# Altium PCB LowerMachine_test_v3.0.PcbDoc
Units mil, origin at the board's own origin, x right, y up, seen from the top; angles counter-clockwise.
Board outline 1968.5 x 1968.5 mil, 2 copper layers (Top Layer, Bottom Layer); 43 components, 58 nets, 180 pads, 51 vias.
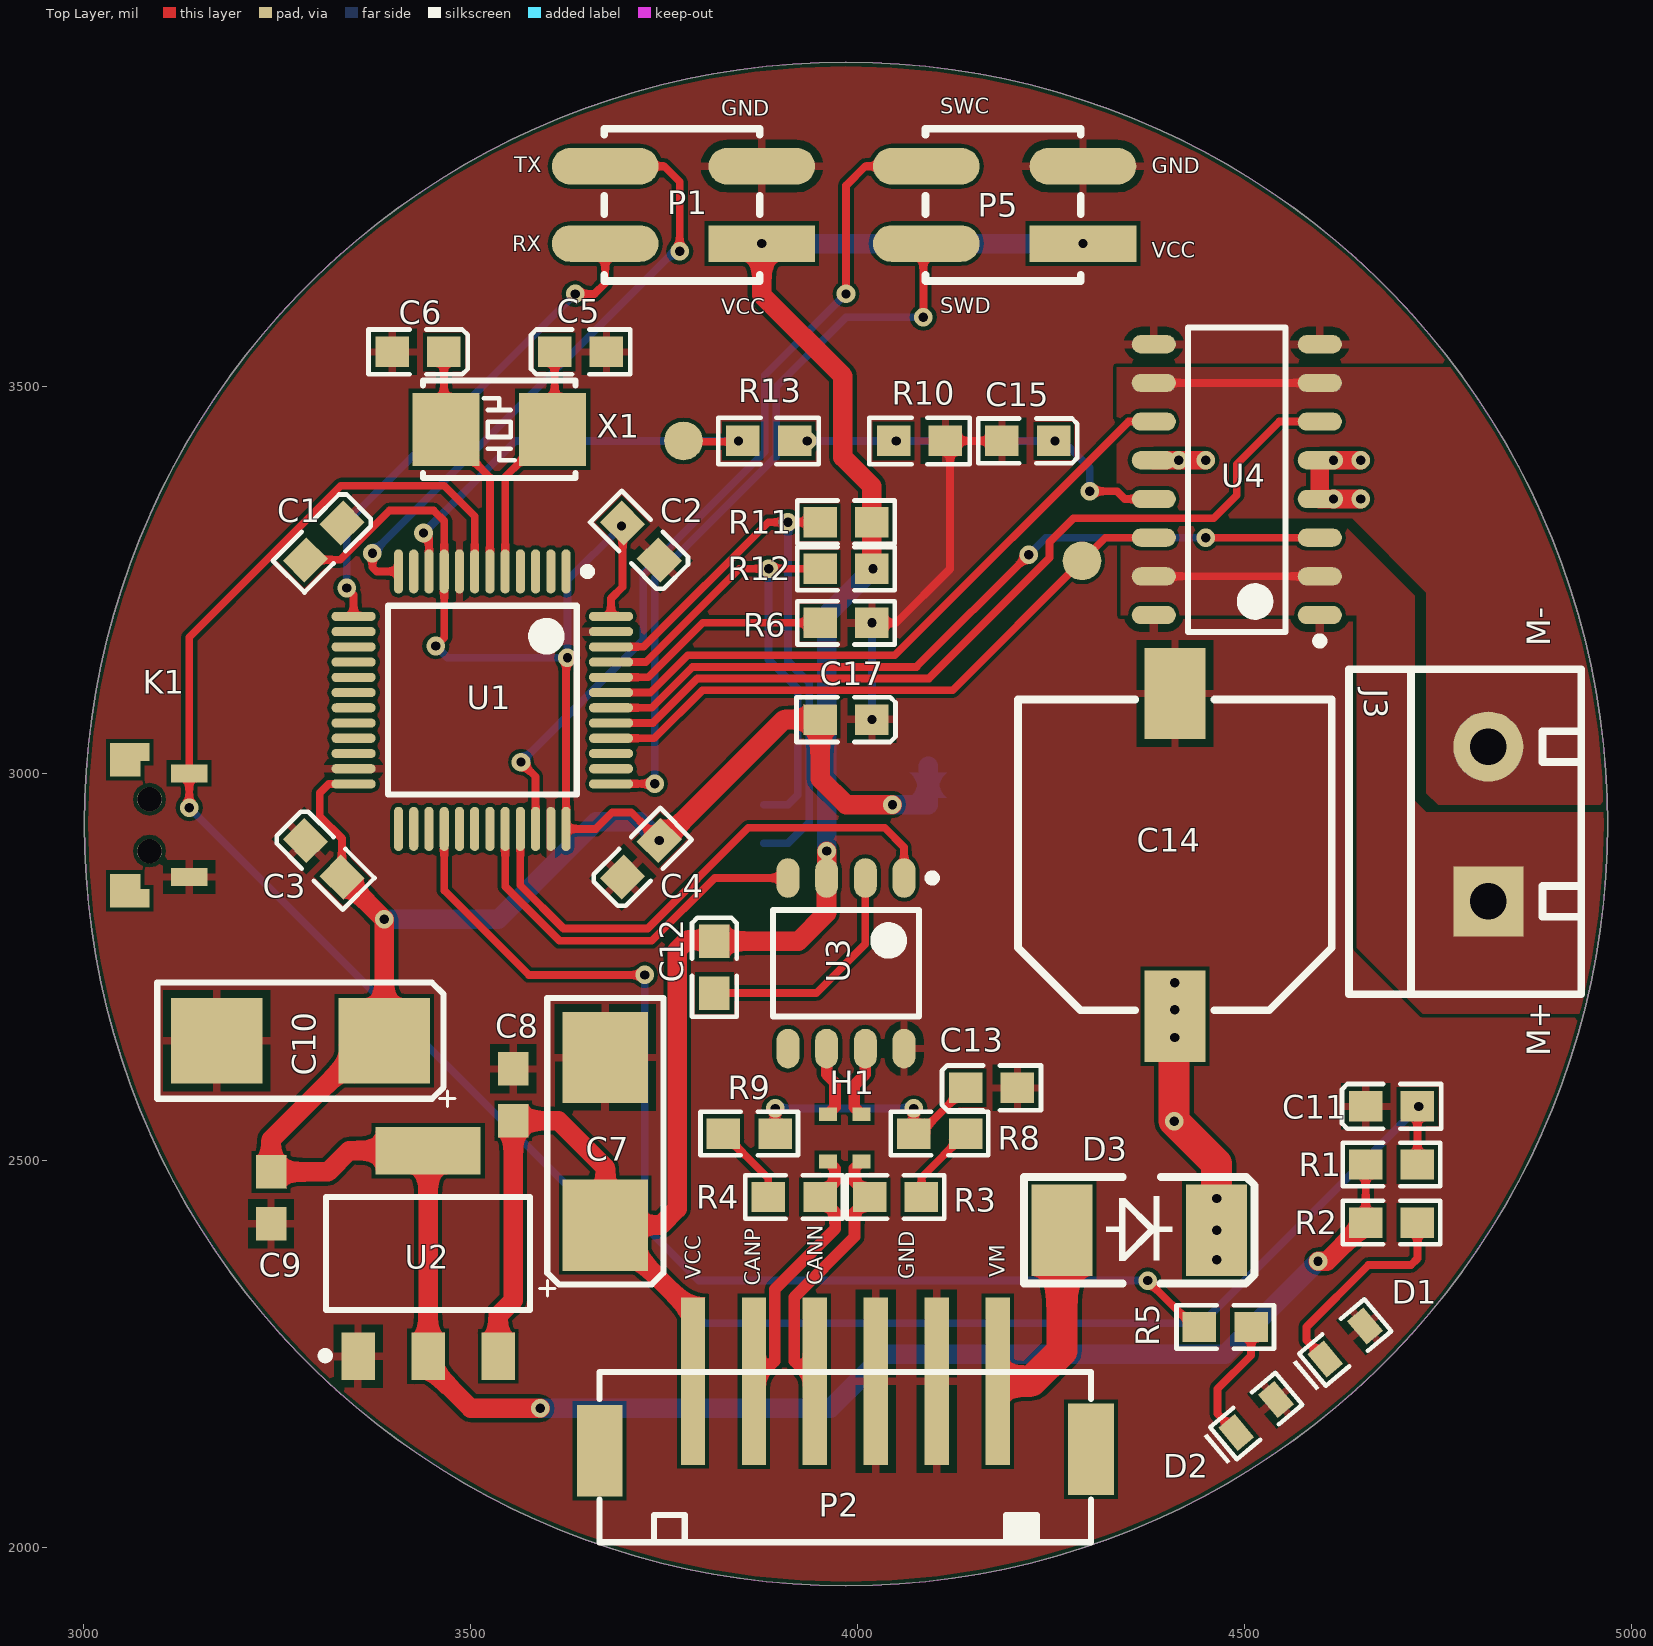
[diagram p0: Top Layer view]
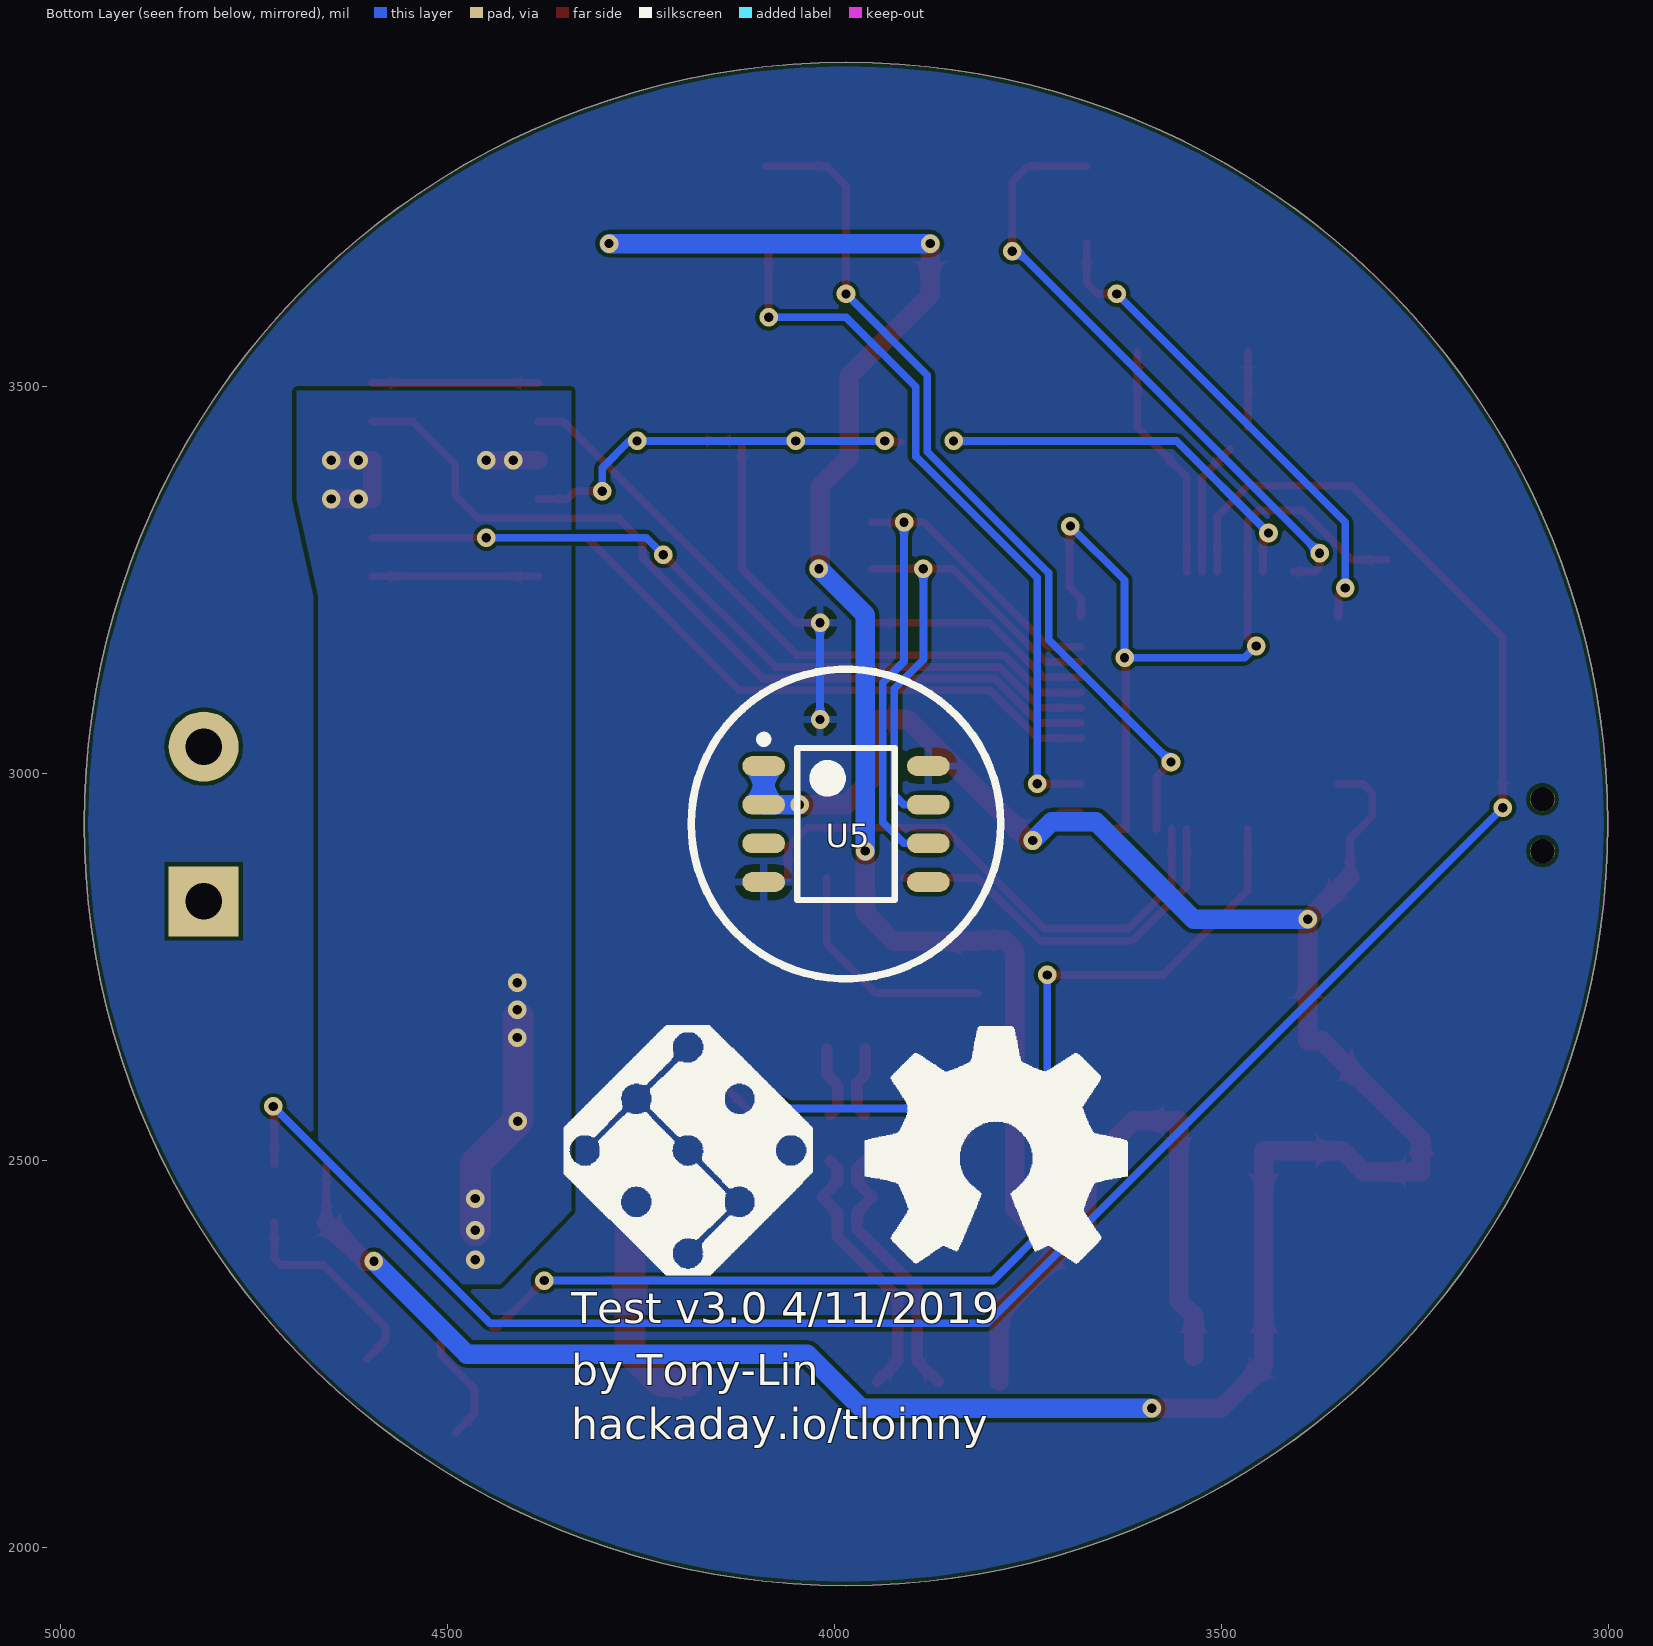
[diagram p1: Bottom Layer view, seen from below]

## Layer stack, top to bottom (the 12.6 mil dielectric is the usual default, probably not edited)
Top Solder: solder mask 0.4, Solder Resist, Dk 3.5
Top Layer: signal copper 1.4
Dielectric 1: dielectric 12.6, FR-4, Dk 4.8
Bottom Layer: signal copper 1.4
Bottom Solder: solder mask 0.4, Solder Resist, Dk 3.5

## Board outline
3000.75,2935 ccw(c3985,2935) 3985,1950.75 ccw(c3985,2935) 4969.25,2935 ccw(c3985,2935) 3985,3919.25 ccw(c3985,2935)

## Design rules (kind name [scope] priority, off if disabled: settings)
Clearance [All] p1: gap=5
DiffPairsRouting [All] p1: maxlimit=10 minlimit=10 mostfreqgap=10 toplayer_minwidth=15 toplayer_maxwidth=15 toplayer_prefwidth=15 bottomlayer_minwidth=15 bottomlayer_maxwidth=15 bottomlayer_prefwidth=15 maxuncoupledlength=500
PolygonConnect PolygonConnect_3 [InNet('24V')] p1: connectstyle=Direct reliefconductorwidth=10 reliefentries=4 polygonreliefangle="90 Angle" airgapwidth=10
PolygonConnect PolygonConnect_2 [InNet('GND')] p2: connectstyle=Relief reliefconductorwidth=10 reliefentries=4 polygonreliefangle="90 Angle" airgapwidth=10
PolygonConnect PolygonConnect_1 [InNet('M+')] p3: connectstyle=Direct reliefconductorwidth=10 reliefentries=4 polygonreliefangle="90 Angle" airgapwidth=10
PolygonConnect [InNet('M-')] p4: connectstyle=Direct reliefconductorwidth=10 reliefentries=4 polygonreliefangle="90 Angle" airgapwidth=10
RoutingVias [All] p1: holewidth=28 width=50 viastyle="Through Hole" minholewidth=28 minwidth=50 maxholewidth=28 maxwidth=50
SolderMaskExpansion [All] p1: expansion=4
Width [All] p1: maxlimit=40 minlimit=6 preferedwidth=10
29 further rules are at their usual default settings.

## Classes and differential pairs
differential pair IN: +IN_P -IN_N
differential pair CAN: +CAN_P -CAN_N

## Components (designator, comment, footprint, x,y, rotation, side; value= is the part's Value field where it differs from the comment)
C1 "104" Cap-0603 3310,3300 r225 top
C2 "104" Cap-0603 3720,3300 r135 top
C3 "104" Cap-0603 3310,2890 r315 top
C4 "104" Cap-0603 3720,2890 r45 top
C5 "22pf" Cap-0603 3642,3545 r0 top
C6 "22pf" Cap-0603 3432,3545 r180 top
C7 "100uf" tan_cap_C 3674,2525 r90 top
C8 "104" Cap-0603-M 3555,2585 r270 top
C9 "104" Cap-0603-M 3242,2452 r90 top
C10 "100uf" tan_cap_C 3280,2655 r180 top
C11 "105" Cap-0603 4690,2570 r0 top
C12 "104" Cap-0603 3815,2750 r270 top
C13 "100nf" Cap-0603 4173,2594 r0 top
C14 "35v 470uf" CAPE_G_10X10.3X10.2 4410,2895 r270 top
C15 "10nf" Cap-0603 4220,3430 r180 top
C17 "100nf" Cap-0603 3985,3070 r180 top
D1 "LED_SMD_BLUE" LED_0603_B 4630,2265 r40 top
D2 "LED_SMD_WHITE" LED_0603_W 4515,2170 r40 top
D3 "1N5824" DO-214AC/SMA 4269,2410 r0 top
H1 "共模扼流圈" 共模扼流圈 4005,2560 r270 top
J3 "Motor interface" KF301-5.0-2P 4815,2835 r90 top
K1 "KEY" SW-SMD-2X4 3085,2900 r90 top
P1 "Header_2X2" Header_SMD_2.54X2 3775,3735 r90 top
P2 "PH2.0-6P" PH2.0S-6P 4181,2215 r180 top
P5 "Header_2X2" Header_SMD_2.54X2 4190,3735 r90 top
R1 "10K" Res-0603 4690,2495 r0 top
R2 "470R" Res-0603 4690,2420 r0 top
R3 "60R" Res-0603 4049,2453 r0 top
R4 "60R" Res-0603 3918,2453 r0 top
R5 "470" Res-0603 4475,2285 r0 top
R6 "10K" Res-0603 3985,3195 r180 top
R8 "0R" Res-0603 4106,2535 r180 top
R9 "0R" Res-0603 3860,2535 r180 top
R10 "1K" Res-0603 4080,3430 r180 top
R11 "4.7K" Res-0603 3985,3325 r180 top
R12 "4.7K" Res-0603 3985,3265 r180 top
R13 "10K" Res-0603 3885,3430 r0 top
U1 "stm32f103c8t6" stm32f103c8t6 3515,3095 r270 top
U2 "AMS1117" AMS1117 3445,2380 r0 top
U3 "tja1050" tja1050 3985,2755 r270 top
U4 "VNH7100" VNH7100 4490,3380 r180 top
U5 "AS5600" AS5600 3985,2935 r180 bottom
X1 "XTAL-2P" "OSC 5032-2P" 3537,3445 r0 top

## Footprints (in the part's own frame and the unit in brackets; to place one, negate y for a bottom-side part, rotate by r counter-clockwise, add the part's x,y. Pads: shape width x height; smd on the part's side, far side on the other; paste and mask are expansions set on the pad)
AMS1117 [mm]
  rect 1.1x1.55 smd: 1(-2.3,-3.375) 2(0,-3.375) 3(2.3,-3.375)
  rect 3.45x1.55 smd: 4(0,3.375)
  silkscreen extent -3.5,-3.48 3.35,1.85, body extent -3.25,-3.48 3.25,3.48, height 1.7
AS5600 [mm] "SOIC, 8-Leads, Body 4.90x3.90mm, Pitch 1.27mm, Thermal Pad 0.00x0.00mm, IPC Medium Density"
  oval 1.4x0.65 smd: 1(-2.7,1.905) 2(-2.7,0.635) 3(-2.7,-0.635) 4(-2.7,-1.905) 5(2.7,-1.905) 6(2.7,-0.635) 7(2.7,0.635) 8(2.7,1.905)
  silkscreen extent -2.83,-2.5 1.6,2.9, body extent -2,-2.5 2,2.5, height 1.75
Cap-0603 [mm]
  rect 1.1x1 smd: 1(-0.85,0) 2(0.85,0)
  silkscreen extent -1.63,-0.74 1.63,0.74, body extent -0.8,-0.4 0.8,0.4, height 0.6
Cap-0603-M [mm]
  rect 1.1x1 smd: 1(-0.85,0) 2(0.85,0)
  body extent -0.8,-0.4 0.8,0.4, height 0.6
CAPE_G_10X10.3X10.2 [mm]
  rect 3x2 smd: 1(5.3,0) 2(-5.3,0)
  silkscreen extent -5.1,-5.15 5.1,5.15, body extent -5.8,-5.15 5.8,5.15, height 10.2
DO-214AC/SMA [mm] "塑封二极管"
  rect 2x3 smd: A(-0.127,0) K(4.953,0)
  silkscreen extent -1.37,-1.75 6.2,1.75, body extent 0.11,-1.35 4.71,1.35, height 2.4
Header_SMD_2.54X2 [mm]
  rect 1.2x3.5 smd: 1(-1.27,-2.57)
  oval 1.2x3.5 smd: 2(1.27,-2.57) 3(1.27,2.57) 4(-1.27,2.57)
  silkscreen extent -2.5,-2.5 2.5,2.6, body extent -2.58,-3.75 2.5,3.75, height 9.7
KF301-5.0-2P [mm] "可拼接端子/6A"
  rect 2.3x2.3 hole 1.2: 1(0,0)
  round 2.3 hole 1.2: 2(5.08,0)
  silkscreen extent -3.05,-3.05 7.62,4.57, body extent -3,-3.09 7.5,4.51, height 10.05
LED_0603_B [mm]
  rect 0.7x1 smd: 1(-0.85,0) 2(0.85,0)
  silkscreen extent -1.75,-0.69 1.4,0.69, body extent -0.8,-0.42 0.8,0.38, height 0.61
LED_0603_W [mm]
  rect 0.7x1 smd: 1(-0.85,0) 2(0.85,0)
  silkscreen extent -1.75,-0.69 1.4,0.69, body extent -0.8,-0.42 0.8,0.38, height 0.61
"OSC 5032-2P" [mm]
  rect 2.2x2.4 smd: 1(-1.75,0) 2(1.75,0)
  silkscreen extent -2.5,-1.6 2.5,1.6, body extent -2.5,-1.52 2.5,1.68, height 0.86
PH2.0S-6P [mm]
  rect 1.5x3 smd: 0(-3.064,2.238) 0(13.064,2.286)
  rect 0.8x5.5 smd: 1(0,0) 2(2,0) 3(4,0) 4(6,0) 5(8,0) 6(10,0)
  silkscreen extent -3.06,-0.3 13.06,5.29, body extent -3,-2.5 13,5.3, height 6.15
Res-0603 [mm]
  rect 1.1x1 smd: 1(-0.85,0) 2(0.85,0)
  silkscreen extent -1.6,-0.71 1.6,0.71, body extent -0.8,-0.4 0.8,0.4, height 0.38
stm32f103c8t6 [mm] "QFP, 100-Leads, Body 14.00x20.00mm, Pitch 0.65mm, IPC Medium Density"
  oval 1.45x0.3 smd: 1(-4.225,2.75) 2(-4.225,2.25) 3(-4.225,1.75) 4(-4.225,1.25) 5(-4.225,0.75) 6(-4.225,0.25) 7(-4.225,-0.25) 8(-4.225,-0.75) 9(-4.225,-1.25) 10(-4.225,-1.75) 11(-4.225,-2.25) 12(-4.225,-2.75) 25(4.225,-2.75) 26(4.225,-2.25) 27(4.225,-1.75) 28(4.225,-1.25) 29(4.225,-0.75) 30(4.225,-0.25) 31(4.225,0.25) 32(4.225,0.75) 33(4.225,1.25) 34(4.225,1.75) 35(4.225,2.25) 36(4.225,2.75)
  oval 0.3x1.45 smd: 13(-2.75,-4.225) 14(-2.25,-4.225) 15(-1.75,-4.225) 16(-1.25,-4.225) 17(-0.75,-4.225) 18(-0.25,-4.225) 19(0.25,-4.225) 20(0.75,-4.225) 21(1.25,-4.225) 22(1.75,-4.225) 23(2.25,-4.225) 24(2.75,-4.225) 37(2.75,4.225) 38(2.25,4.225) 39(1.75,4.225) 40(1.25,4.225) 41(0.75,4.225) 42(0.25,4.225) 43(-0.25,4.225) 44(-0.75,4.225) 45(-1.25,4.225) 46(-1.75,4.225) 47(-2.25,4.225) 48(-2.75,4.225)
  silkscreen extent -4.35,-3.1 3.1,3.58, body extent -3.5,-3.5 3.5,3.5, height 1.6
SW-SMD-2X4 [mm]
  rect 0.6x1.3 smd: 0(-1.55,0.65) 0(3.25,0.65)
  rect 0.6x1 smd: 0(-1.05,0.8) 0(2.75,0.8)
  round 0.8 hole 0.8: 0(0,0) 0(1.7,0)
  rect 0.6x1.2 smd: 1(-0.85,-1.3) 3(2.55,-1.3)
  body extent -2.97,-1.8 4.83,1.8, height 3.5
tan_cap_C [mm]
  rect 3x2.8 smd: 1(-2.75,0) 2(2.75,0)
  silkscreen extent -5.08,-1.91 4.7,2.16, body extent -3.15,-1.6 3.15,1.6, height 2.5
tja1050 [mm] "SOP, 8-Leads, Body 4.90x3.90mm, Pitch 1.27mm, IPC Medium Density"
  oval 1.3x0.75 smd: 1(-2.8,1.905) 2(-2.8,0.635) 3(-2.8,-0.635) 4(-2.8,-1.905) 5(2.8,-1.905) 6(2.8,-0.635) 7(2.8,0.635) 8(2.8,1.905)
  silkscreen extent -2.92,-2.4 1.75,2.96, body extent -1.9,-2.4 1.9,2.4, height 1.75
VNH7100 [mm] "SOIC, 16-Leads, Body 9.90x3.90mm, Pitch 1.27mm, IPC Medium Density"
  oval 1.45x0.6 smd: 1(-2.725,4.445) 2(-2.725,3.175) 3(-2.725,1.905) 4(-2.725,0.635) 5(-2.725,-0.635) 6(-2.725,-1.905) 7(-2.725,-3.175) 8(-2.725,-4.445) 9(2.725,-4.445) 10(2.725,-3.175) 11(2.725,-1.905) 12(2.725,-0.635) 13(2.725,0.635) 14(2.725,1.905) 15(2.725,3.175) 16(2.725,4.445)
  silkscreen extent -2.85,-5 1.6,5.42, body extent -2,-5 2,5, height 1.75
共模扼流圈 [mm]
  rect 0.45x0.6 smd: 1(0,0) 2(0,-1.1) 3(1.55,-1.1) 4(1.55,0)

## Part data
C1 C2 C3 C4 C5 C6 C8 C9 C11 C12 C13: library part CAP
C7 C10: library part tan_cap
C14: library part CAPE-SMD, "贴片电解电容"
C15 C17: library part CAP, "贴片陶瓷电容"
D1 D2: "发光二极管"
D3: library part DIODE, "普通二极管"
J3: library part KF301-2P
R1 R2 R3 R4 R5 R6 R8 R9 R10 R11 R12 R13: library part RES, "贴片电阻"
X1: "2脚无源脚晶振"

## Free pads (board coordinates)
  round 50 smd: 1(4290,3275) 2(3775,3430)

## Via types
v1: diameter 24, hole 12, Top Layer to Bottom Layer, 51 vias

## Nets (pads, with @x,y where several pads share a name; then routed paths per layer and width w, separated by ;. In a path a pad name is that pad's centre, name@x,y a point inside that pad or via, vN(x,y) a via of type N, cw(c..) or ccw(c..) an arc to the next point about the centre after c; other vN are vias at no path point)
3.3V: C1.2 C2.2 C3.2 C4.2 C9.2 C10.1 C17.2 R1.1 R2.1 U1.9 U1.24 U1.36 U1.48 U2.2 U2.4 U5.1 U5.2 | length 4760.9
  Top Layer w10: C1.2 3331.34,3276.34 3395,3340 3452.37,3340 3465.79,3326.59 U1.9 3465.79,3175.79 v1(3455,3165) ; C3.2 3333.66,2916.34 3305,2945 3305,2975 3316.73,2986.73 U1.24 ; v1(3625,3150) 3623.27,3148.27 U1.36 3661.66,2928.66 3683,2950 3707.33,2950 v1(3743.66,2913.66) ; U1.48 3681.34,3226.34 3696.34,3241.34 C2.2 ; R2.1 R1.1
  Top Layer w25: C3.2 v1(3388.27,2811.73) C10.1 3370,2655 3242,2527 C9.2 3315.46,2485.46 3342.87,2512.87 U2.4 U2.2 3445,2235 3500,2180 v1(3590,2180) ; v1(3743.66,2913.66) 3748.66,2913.66 3905,3070 C17.2 3951.54,2993.46 3985,2960 v1(4045,2960) ; v1(4595,2370) 4606.54,2370 R2.1
  Bottom Layer w10: v1(3455,3165) 3470,3150 v1(3625,3150) 3625,3250 v1(3695,3320)
  Bottom Layer w25: v1(3388.27,2811.73) 3535.73,2811.73 3662,2938 3719.33,2938 v1(3743.66,2913.66) ; v1(3590,2180) 3965,2180 4035,2250 4475,2250 v1(4595,2370) ; v1(4045,2960) U5.2 U5.1
24V: C14.1 D3.K U4.4 U4.5 U4.12 | length 520.8
  Top Layer w24: U4.12 v1(4450,3405) ; v1(4650,3355) U4.4 U4.5 v1(4650,3405)
  Top Layer w40: C14.1@4409,2685.34 4409,2592.34 v1(4409,2551) 4464,2496 v1(4464,2410)
  other v1: 4464,2372 4464,2451 4410,2659 4410,2695 4410,2730 4615,3355 4415,3405 4615,3405
ADC: pad.2 R13.1 U1.10 | length 585.4
  Top Layer w10: v1(3439,3311) 3446.1,3303.9 U1.10 ; pad.2 3776,3429 R13.1@3846.54,3429 ; v1(3846,3430) R13.1@3850.54,3430
  Bottom Layer w10: v1(3439,3311) 3558,3430 3775,3430 v1(3846,3430)
BOOT0: R6.2 U1.44 | length 299.4
  Top Layer w10: U1.44 3729.27,3124.53 3799.75,3195 R6.2
BOOT1: U1.20
CAN_N: H1.4 P2.4 R3.1 | length 347.7
  Top Layer w15: P2.4 3937.28,2222.5 3936.5,2222.5 3918,2241 3918,2323.64 3996,2401.64 3996,2433.46 R3.1 3996,2472.54 3996,2489.98 H1.4
CAN_P: H1.3 P2.5 R4.2 | length 348.1
  Top Layer w15: P2.5 3873.54,2222.5 3874.5,2222.5 3893,2241 3893,2334 3971,2412 3971,2433.46 R4.2 3971,2472.54 3971,2489.67 H1.3
CAN_RX: U1.32 U3.4 | length 502.6
  Top Layer w10: U1.32 3544.53,2854.26 3614.79,2784 3734,2784 3815.24,2865.24 U3.4
CAN_TX: U1.33 U3.1 | length 695.7
  Top Layer w10: U1.33 3564.21,2855.79 3620,2800 3728.79,2800 3858.79,2930 4035,2930 4060,2905 U3.1
GND: C1.1 C2.1 C3.1 C4.1 C5.2 C6.2 C7.2 C8.1 C9.1 C10.2 C11.1 C13.2 C14.2 C15.2 C17.1 D1.2 D2.2 K1.1 P1.2 P2.2 P2.3 P5.2 R6.1 R10.1 U1.8 U1.23 U1.35 U1.47 U2.1 U3.8 U4.1 U4.8 U4.9 U4.16 U5.4 U5.8 | length 492.4
  Top Layer w10: v1(4018.46,3195) 4050,3195 4119.46,3264.46 R10.1@4119.46,3429 ; R10.1 C15.2
  Bottom Layer w10: v1(4018.46,3070) v1(4018.46,3195)
IN_N: H1.1 U3.7 | length 94.4
  Top Layer w15: H1.1 3995.85,2569.15 3995.85,2597.52 4010,2611.67 U3.7
IN_P: H1.2 U3.6 | length 93
  Top Layer w15: U3.6 3960,2611.67 3970.85,2600.83 3970.85,2569.15 H1.2
JTCK: P5.4 U1.37 | length 958.7
  Top Layer w10: U1.37 3681.61,2987 v1(3738,2987) ; v1(4085,3590) 4085,3681.18 P5.4
  Bottom Layer w10: v1(3738,2987) 3738,3253 3895,3410 3895,3500 3985,3590 v1(4085,3590)
JTMS: P5.3 U1.34 | length 1127.3
  Top Layer w10: v1(3565,3015) 3583.9,2996.1 U1.34 ; v1(3985,3620) 3985,3760 4010,3785 P5.3
  Bottom Layer w10: v1(3565,3015) 3723,3173 3723,3259.21 3880,3416.21 3880,3515 v1(3985,3620)
M+: J3.1 U4.2 U4.15 | length 214.6
  Top Layer w10: U4.15 U4.2
M-: J3.2 U4.7 U4.10 | length 214.6
  Top Layer w10: U4.10 U4.7
NetC12_2: C12.2 U3.2 | length 306.5
  Top Layer w10: C12.2 3946.54,2716.54 4010,2780 U3.2
NetC13_1: C13.1 R8.2 R9.1 | length 335.3
  Top Layer w10: R9.1 v1(3893.46,2567.46) ; R8.2@4072.46,2535.07 v1(4072.46,2567.46) ; R8.2 4080.54,2535 C13.1
  Bottom Layer w10: v1(3893.46,2567.46) v1(4072.46,2567.46)
NetC15_1: C15.1 R10.2 R13.2 U4.13 | length 516.9
  Top Layer w10: R13.2@3913.46,3429 R13.2@3934,3429 ; v1(4300,3365) 4335.2,3365 4345.2,3355 U4.13
  Bottom Layer w10: v1(3935,3430) v1(4050,3430) 4265,3430 4300,3395 v1(4300,3365)
  other v1: 4255,3430
NetD1_1: D1.1 R2.2 | length 278.2
  Top Layer w10: D1.1 4580,2267.86 4580,2285 4660,2365 4715,2365 4723.46,2373.46 R2.2
NetD2_1: D2.1 R5.2 | length 164.6
  Top Layer w10: D2.1 4465,2172.86 4465,2205 4508.46,2248.46 R5.2
NetD3_A: D3.A P2.1 | length 246.2
  Top Layer w40: P2.1@4190,2215 4225,2215 4264,2254 D3.A
NetR3_2: R3.2 R8.1 | length 105.6
  Top Layer w10: R3.2 4082.46,2478 R8.1
NetR4_1: R4.1 R9.2 | length 106
  Top Layer w10: R9.2 3884.54,2477 R4.1
NRST: C11.2 K1.3 R1.2 U1.7 | length 2820.4
  Top Layer w10: v1(3136.18,2956.18) K1.3 3136.18,3176.18 3332,3372 3465.63,3372 3505.16,3332.47 U1.7 ; R1.2 C11.2
  Bottom Layer w10: v1(3136.18,2956.18) 3802.36,2290 4445,2290 v1(4725,2570) v1@4720,2565
OSC8M_IN: C5.1 U1.5 X1.2 | length 303.8
  Top Layer w10: U1.5 3544.53,3383.63 X1.2@3604,3443.1 ; X1.2@3608.54,3447.64 C5.1
OSC8M_OUT: C6.1 U1.6 X1.1 | length 270.6
  Top Layer w10: X1.1@3465.46,3447.64 C6.1 ; X1.1@3488.46,3419.54 3524.84,3383.16 U1.6
OSC32_IN: U1.3
OSC32_OUT: U1.4
PA1: U1.11
PA2: P1.3 U1.12 | length 807.1
  Top Layer w10: v1(3373,3285) 3373,3267 3378.66,3261.34 U1.12 ; P1.3 3750,3785 3770,3765 v1(3770,3675)
  Bottom Layer w10: v1(3373,3285) 3763,3675 v1(3770,3675)
PA3: P1.4 U1.13 | length 638.2
  Top Layer w10: v1(3340,3240) 3348.66,3231.34 U1.13 ; v1(3635,3620) 3660,3620 3673.82,3633.82 P1.4
  Bottom Layer w10: v1(3340,3240) 3340,3325 v1(3635,3620)
PA4: U1.14
PA5: U1.15
PA6: U1.16
PA7: U1.17
PA8: U1.29
PA9: U1.30
PA10: U1.31
PA15: U1.38
PB0: U1.18
PB1: U1.19
PB3: U1.39
PB4: pad.1 U1.40 U4.14 | length 808.7
  Top Layer w10: U1.40 3737.29,3045.79 3799.5,3108 4123,3108 pad.1 4320,3305 U4.14
PB5: U1.41 U4.6 | length 1112.5
  Top Layer w10: U1.41 3735.47,3065.47 3793,3123 4092.11,3123 4248,3278.89 4248,3299 4279,3330 4460,3330 4490,3360 4490,3400 4545,3455 U4.6
PB6: U1.42 U4.3 | length 1007
  Top Layer w10: U1.42 3733.94,3085.16 3786.79,3138 4076,3138 v1(4221,3283) ; v1(4450,3305) U4.3
  Bottom Layer w10: v1(4221,3283) 4243,3305 v1(4450,3305)
PB7: U1.43 U4.11 | length 846.4
  Top Layer w10: U1.43 3732.22,3104.84 3780.37,3153 4048,3153 4350,3455 U4.11
PB8: R12.2 U1.45 U5.7 | length 677.2
  Top Layer w10: U1.45 3726.33,3144.21 3847.12,3265 v1(3885,3265) R12.2
  Bottom Layer w10: U5.7 3910,2960 3922.5,2972.5 3922.5,3109.87 3885,3147.37 v1(3885,3265)
PB9: R11.2 U1.46 U5.6 | length 806
  Top Layer w10: U1.46 3723.39,3163.9 3884.49,3325 v1(3910,3325) R11.2
  Bottom Layer w10: U5.6 3910,2910 3937.5,2937.5 3937.5,3117.5 3910,3145 v1(3910,3325)
PB10: U1.21
PB11: U1.22
PB12: U1.25
PB13: U1.26
PB14: U1.27
PB15: R5.1 U1.28 | length 1479.3
  Top Layer w10: U1.28 3465.79,2849.21 3575,2740 v1(3725,2740) ; v1(4375,2345) 4435,2285 R5.1
  Bottom Layer w10: v1(3725,2740) 3725,2415 3795,2345 v1(4375,2345)
PC13: U1.2
VBAT: U1.1
VCC: C7.1 C8.2 C12.1 P1.1 P2.6 P5.1 R11.1 R12.1 U2.3 U3.3 | length 2793.2
  Top Layer w25: U2.3 3535.55,2300 3555,2319.45 C8.2 3613.46,2551.54 3674,2491 C7.1 ; P2.6 3787.3,2303.43 C7.1 ; v1(3876.18,3685) 3876.18,3618.59 3981,3513.77 3981,3409 4018.46,3371.54 R11.1 R12.1 ; v1(3960,2900) U3.3 3960,2820 3923.5,2783.5 C12.1 C12.1 3813.46,2785 3780,2785 3767,2772 3767,2438 3745.73,2416.73 C7.1
  Bottom Layer w25: v1(3876.18,3685) v1(4291.18,3685) ; v1(3960,2900) 3960,3205 v1(4020,3265)
pads on no net: K1.0 P2.0 U3.5 U5.3 U5.5

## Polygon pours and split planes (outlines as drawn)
GND on Bottom Layer "Top Layer-No Net" (solid, remove dead copper, pour order 24): 2916,3946 2916,1768 2814,1666 2956,1808 5468,1808 5468,3536 4923,4081
24V on Bottom Layer "Top Layer-No Net" (solid, remove dead copper, pour order 16): 4695,3495 4695,3355 4675,3265 4667.12,3229.53 4667.12,2340 4431.61,2340 4340,2435 4340,2470 4340,3495
GND on Top Layer "Top Layer-No Net" (solid, remove dead copper, pour order 22): 2873,3955 2883,3945 2883,1823 5248,1823 5302,1877 5214,1965 5214,4024
M+ on Top Layer "Top Layer-No Net" (solid, remove dead copper, pour order 20): 4340,3320 4340,3205 4645,3205 4645,2775 4730,2690 5085,2690 5085,2935 5080,2940 5070,2950 4740,2950 4735,2950 4720,2965 4720,3230 4630,3320
M- on Top Layer "Top Layer-No Net" (solid, remove dead copper, pour order 18): 4335,3525 4335,3340 4345,3330 4639.12,3330 4735,3234.12 4735,2975 4750,2960 4990,2960 4990,3510 4975,3525

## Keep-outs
Keep-Out Layer:
  circle w0.5: c3985,2935 r984.25

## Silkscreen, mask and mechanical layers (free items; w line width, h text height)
Top Overlay:
  lines w5: 3392.95,3217.05 3392.95,3217.05 ; 3637.05,2972.95 3637.05,2972.95
  text "SWC" at 4107,3853 h20
  text "GND" at 3824,3850 h20
  text "TX" at 3556,3777 h20
  text "GND" at 4380,3776 h20
  text "RX" at 3554,3675 h20
  text "VCC" at 4380,3667 h20
  text "SWD" at 4107,3595 h20
  text "VCC" at 3824,3594 h20
  text "M-" at 4895,3165 h30 r90
  text "M+" at 4895,2635 h30 r90
  text "VM" at 4190,2349 h20 r90
  text "VCC" at 3797,2347 h20 r90
  text "GND" at 4073,2347 h20 r90
  text "CANN" at 3955,2339 h20 r90
  text "CANP" at 3874,2338 h20 r90
Bottom Overlay:
  drawing of 1396 lines, arcs and shapes, not listed
  text "Test v3.0 4/11/2019" at 4340,2290 h40
  text "by Tony-Lin" at 4340,2210 h40
  text "hackaday.io/tloinny" at 4340,2140 h40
